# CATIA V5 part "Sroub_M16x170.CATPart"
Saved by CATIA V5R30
Part number: Sroub_M16x170
Definition: E 1200_16x170_3
Nomenclature: E 1200_16x170_3
Source: Unknown
Description: PART--DESC
Bounding box of the stored display mesh (mm): x -152 to -128, y -148.99 to -125.01, z -259 to -73
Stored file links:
  E:\Bakalarka\Model\Forma_v7\Sroub_M16x170.CATPart
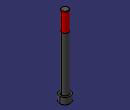
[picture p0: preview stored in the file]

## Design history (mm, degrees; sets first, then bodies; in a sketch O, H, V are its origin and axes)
Body1 "MANIFOLD_SOLID_BREP #3786" (main body)
  Solid1: solid without history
